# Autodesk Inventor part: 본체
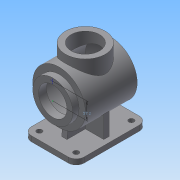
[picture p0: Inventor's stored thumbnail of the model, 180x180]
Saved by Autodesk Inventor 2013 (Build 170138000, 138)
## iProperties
Created: 2016-09
Part Number: 본체
Material: 일반
Document SubType Name: Modeling
Designer: Administrator
Density: 1 g/cm^3
Author: Administrator
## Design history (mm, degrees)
sketch "스케치1"
  geometry: L1 (-62, 38)-(-62, 27); L2 (-62, 27)-(-47, 27); L3 (-47, 27)-(-47, 47); L4 (-47, 47)-(46.661, 47); L5 (-62, 38)-(-50, 38); L6 (-50, 38)-(-50, 50); L7 (-50, 50)-(48.562, 50); L8 (57, 0)-(60, 0); A1 r 115 centre (-55, 0) between (60, 0) and (48.562, 50); A2 r 112 centre (-55, 0) between (57, 0) and (46.661, 47); 1 further point
  constraints: 16 end point, 4 parallel, 4 point on circle, 2 centre point, 2 perpendicular, 1 horizontal alignment, 1 point on line, 1 vertical
  dimensions: "d0" = 115 radius of A1; "d2" = 3 radial gap between concentric circles of A1 A2; "d3" = 54 diameter of L2 L8; "d4" = 76 diameter of L5 L8; "d5" = 100 diameter of L7 L8; "d6" = 94 diameter of L4 L8; "d7" = 15 distance between parallel lines of L3 L1; "d8" = 12 distance between parallel lines of L6 L1; "d9" = 110 distance from line of L8.end L6; "d51" = 50 distance from line of point (0, 0) L6
revolve "회전1" sketch "스케치1" stored, may be unused: angle "d11" = 90 deg
node "작업 평면1"
sketch "스케치2"
  geometry: L1 (50, 50)-(50, -50) reference; C1 r 38 at (0, 0); 1 further point
  constraints: 1 centre point, 1 coincident
  dimensions: "d13" = 76 diameter of C1; "d15" = 50 distance from line of C1.centre L1
extrude "돌출1" join sketch "스케치2" stored distance "d16" = 10; taper "d17" = 0 deg
hole "구멍1" diameter "d20" = 54; stored, may be unused: countersink angle "d24" = 90 deg, drill point angle "d26" = 118 deg; dims "d18" = 10, "d19" = 10, "d21" = 6, "d22" = 4, "d23" = 2, "d25" = 40
node "작업 평면2"
sketch "스케치6"
  geometry: L1 (-52.5, 50)-(52.5, 50); L2 (67.5, 35)-(67.5, -35); L3 (52.5, -50)-(-52.5, -50); L4 (-67.5, -35)-(-67.5, 35); C1 r 38 at (0, 0) reference; A1 r 15 centre (-52.5, 35) between (-52.5, 50) and (-67.5, 35); A2 r 15 centre (52.5, 35) between (67.5, 35) and (52.5, 50); A3 r 15 centre (52.5, -35) between (52.5, -50) and (67.5, -35); A4 r 15 centre (-52.5, -35) between (-67.5, -35) and (-52.5, -50); 3 further points
  constraints: 8 end point, 8 point on circle, 8 tangent, 4 centre point, 3 equal radius, 2 midpoint, 2 parallel, 1 horizontal, 1 horizontal alignment, 1 perpendicular, 1 vertical alignment
  dimensions: "d37" = 100 distance between parallel lines of L3 L1; "d39" = 135 distance between parallel lines of L4 L2; "d40" = 15 radius of A1
extrude "돌출3" join sketch "스케치6" distance "d41" = 10; taper "d42" = 0 deg
sketch "스케치8"
  geometry: L1 (-82, -35)-(-82, 35) reference; L2 (-82, 35)-(-72, 35) reference; L3 (-72, -35)-(-72, 35) reference; L4 (-82, -35)-(-72, -35) reference; L5 (-72, 40)-(-30, 40); L6 (-72, -40)-(-30, -40); L7 (-72, 40)-(-72, -40); A1 r 50 centre (0, 0) between (-30, 40) and (-30, -40) reference; 1 further point
  constraints: 6 end point, 3 parallel, 2 point on circle, 2 point on line, 1 perpendicular
  dimensions: "d43" = 40 distance from line of point (0, 0) L5
feature "리브1" sketch "스케치8" dims "d44" = 1, "d45" = 10, "d46" = 0, "d47" = 0, "d48" = 1, "d49" = 1
sketch "스케치10"
  geometry: L1 (-50, -50)-(48.562, -50) reference; L2 (52.5, -72)-(-52.5, -72) reference; L3 (-38.075, -50)-(-40, -72); L4 (38.075, -50)-(40, -72); L5 (-38.075, -72)-(40, -72); L6 (-40, -72)-(-38.075, -72); 1 further point
  constraints: 8 end point, 5 point on line, 2 collinear, 1 equal length
  dimensions: "d52" = 95 deg angle of L2 L3; "d53" = 40 horizontal distance of point (0, 0) L3.end; "d54" = 40 horizontal distance of point (0, 0) L4.end
feature "리브3" sketch "스케치10" dims "d61" = 1, "d62" = 10, "d63" = 0, "d64" = 0, "d65" = 1, "d66" = 1
sketch "스케치11"
  geometry: 1 further point
hole "구멍2" diameter "d69" = 10; stored, may be unused: countersink angle "d73" = 90 deg, drill point angle "d75" = 118 deg; dims "d67" = 10, "d68" = 10, "d70" = 6, "d71" = 4, "d72" = 2, "d74" = 40
hole "구멍3" diameter "d78" = 10; stored, may be unused: countersink angle "d82" = 90 deg, drill point angle "d84" = 118 deg; dims "d76" = 10, "d77" = 10, "d79" = 6, "d80" = 4, "d81" = 2, "d83" = 40
hole "구멍4" diameter "d87" = 10; stored, may be unused: countersink angle "d91" = 90 deg, drill point angle "d93" = 118 deg; dims "d85" = 10, "d86" = 10, "d88" = 6, "d89" = 4, "d90" = 2, "d92" = 40
hole "구멍5" diameter "d96" = 10; stored, may be unused: countersink angle "d100" = 90 deg, drill point angle "d102" = 118 deg; dims "d94" = 10, "d95" = 10, "d97" = 6, "d98" = 4, "d99" = 2, "d101" = 40
sketch "스케치12"
  geometry: 2 further points
  constraints: 1 vertical alignment
  dimensions: "d103" = 32.5 distance of point (0, 0) point (0, 32.5)
node "솔리드1"
node "투영된 루프1"
other parameters: "d12" = 65, "d27" = -82
